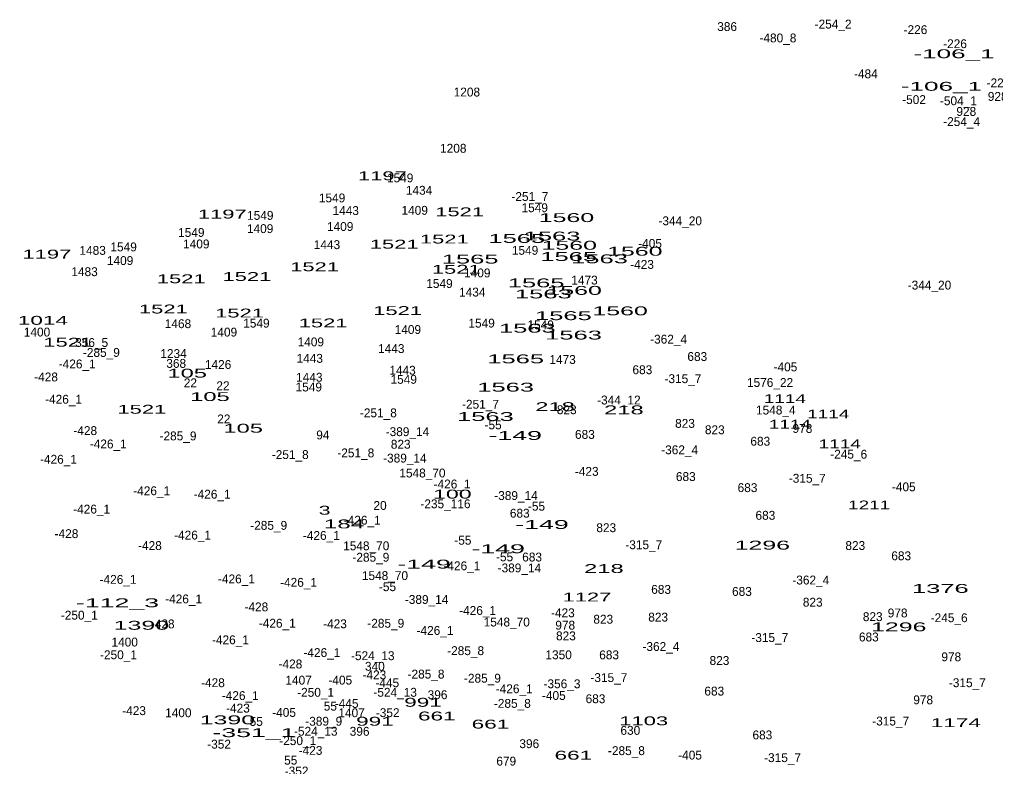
# Model space of a CAD drawing. Extents: x -660434 to -656144, y -997850 to -994016.
# Drawn here: x -659469.4 to -659029.2, y -995192.7 to -994855.8 of the extents above; entities that cross this region are included whole.
import ezdxf
from ezdxf.enums import TextEntityAlignment as Align

# ---------------------------------------------------------------- set-up
doc = ezdxf.new("R2010")
doc.units = 0
doc.header["$LTSCALE"] = 1.6
doc.layers.add('24', color=7, linetype='Continuous')

msp = doc.modelspace()

# ---------------------------------------------------------------- texts
at = {"layer": '24'}
for s, p in [('-254_2', (-659102.467, -994859.81)), ('386', (-659150.263, -994860.94)), ('-226', (-659065.33, -994862.33)), ('-480_8', (-659127.341, -994866.07)), ('-226', (-659047.47, -994868.67)), ('-484', (-659087.693, -994882.26)), ('-226', (-659027.89, -994886.34)), ('1208', (-659267.624, -994890.47)), ('-502', (-659065.959, -994893.88)), ('-504_1', (-659045.954, -994894.4)), ('928', (-659028.223, -994892.44)), ('928', (-659042.393, -994899.22)), ('-254_4', (-659044.491, -994903.8)), ('1208', (-659273.764, -994915.83)), ('1549', (-659297.71, -994929.2)), ('1434', (-659289.199, -994934.78)), ('1549', (-659328.43, -994938.23)), ('-251_7', (-659239.222, -994937.59)), ('1443', (-659322.269, -994943.94)), ('1409', (-659291.164, -994943.82)), ('1549', (-659237.03, -994942.65)), ('1549', (-659360.8, -994946.1)), ('1409', (-659360.864, -994952.08)), ('1409', (-659324.764, -994951.12)), ('-344_20', (-659171.414, -994948.55)), ('1549', (-659391.91, -994953.79)), ('1549', (-659422.44, -994960.32)), ('1409', (-659389.664, -994958.99)), ('1443', (-659330.719, -994959.31)), ('-405', (-659185.023, -994958.75)), ('1483', (-659436.404, -994961.89)), ('1549', (-659241.39, -994961.85)), ('1409', (-659424.034, -994966.48)), ('-423', (-659188.619, -994968.22)), ('1483', (-659440.054, -994971.5)), ('1409', (-659262.944, -994972.05)), ('1549', (-659279.99, -994976.84)), ('1473', (-659214.58, -994975.28)), ('-344_20', (-659058.994, -994977.55)), ('1434', (-659265.189, -994980.69)), ('1468', (-659397.93, -994994.95)), ('1549', (-659362.55, -994994.7)), ('1549', (-659260.98, -994994.7)), ('1549', (-659234.35, -994995.47)), ('1400', (-659461.502, -994998.73)), ('1409', (-659377.184, -994998.75)), ('1409', (-659294.244, -994997.6)), ('-356_5', (-659437.738, -995003.44)), ('1409', (-659338.014, -995003.17)), ('-362_4', (-659176.652, -995001.93)), ('-285_9', (-659432.468, -995007.92)), ('1234', (-659399.934, -995008.44)), ('1443', (-659301.729, -995006.18)), ('683', (-659163.713, -995009.76)), ('-426_1', (-659443.376, -995013.12)), ('368', (-659398.723, -995012.87)), ('1426', (-659379.83, -995013.38)), ('1443', (-659338.489, -995010.59)), ('1473', (-659224.47, -995011.1)), ('1443', (-659296.639, -995015.96)), ('683', (-659188.483, -995015.72)), ('-405', (-659123.963, -995014.45)), ('-428', (-659457.419, -995018.98)), ('22', (-659392.327, -995021.6)), ('22', (-659377.637, -995022.94)), ('1443', (-659338.689, -995019.13)), ('1549', (-659296.11, -995020.05)), ('-315_7', (-659170.182, -995019.75)), ('1576_22', (-659130.889, -995021.47)), ('1549', (-659338.93, -995023.51)), ('-426_1', (-659449.526, -995029.04)), ('-251_7', (-659261.492, -995031.3)), ('-344_12', (-659199.074, -995029.39)), ('-251_8', (-659307.546, -995035.17)), ('823', (-659222.577, -995033.77)), ('1548_4', (-659128.308, -995033.91)), ('22', (-659377.247, -995037.92)), ('-55', (-659255.805, -995040.59)), ('823', (-659169.257, -995039.92)), ('-428', (-659439.749, -995043.18)), ('94', (-659332.587, -995045.14)), ('-389_14', (-659294.435, -995043.66)), ('683', (-659214.403, -995044.9)), ('823', (-659155.817, -995042.8)), ('978', (-659116.288, -995042.22)), ('-426_1', (-659429.366, -995049.21)), ('-285_9', (-659397.908, -995045.57)), ('823', (-659297.467, -995049.33)), ('683', (-659135.303, -995047.98)), ('-251_8', (-659347.296, -995054)), ('-251_8', (-659317.726, -995053.23)), ('-362_4', (-659171.662, -995051.84)), ('-245_6', (-659095.432, -995053.83)), ('-426_1', (-659451.826, -995056.11)), ('-389_14', (-659295.595, -995055.57)), ('1548_70', (-659287.671, -995062.3)), ('-423', (-659213.579, -995061.57)), ('683', (-659168.903, -995063.91)), ('-315_7', (-659114.112, -995064.69)), ('-426_1', (-659409.776, -995070.32)), ('-426_1', (-659274.316, -995067.27)), ('683', (-659141.063, -995068.91)), ('-405', (-659070.583, -995068.54)), ('-426_1', (-659382.516, -995071.86)), ('-389_14', (-659245.475, -995072.47)), ('-426_1', (-659436.856, -995078.59)), ('20', (-659306.781, -995076.96)), ('-235_116', (-659277.295, -995076.19)), ('683', (-659243.783, -995080.43)), ('-55', (-659236.225, -995077.28)), ('-426_1', (-659314.826, -995083.59)), ('683', (-659132.993, -995081.39)), ('-285_9', (-659357.008, -995085.91)), ('823', (-659204.777, -995086.98)), ('-428', (-659448.199, -995089.66)), ('-426_1', (-659391.346, -995090.3)), ('-426_1', (-659333.266, -995090.47)), ('-55', (-659269.435, -995092.64)), ('-428', (-659410.569, -995095.04)), ('1548_70', (-659313.011, -995095.14)), ('-315_7', (-659187.842, -995094.66)), ('823', (-659092.457, -995095.02)), ('-285_9', (-659310.928, -995100.31)), ('-55', (-659250.625, -995100.13)), ('683', (-659238.213, -995100.21)), ('683', (-659071.743, -995099.65)), ('-426_1', (-659269.876, -995104.16)), ('-389_14', (-659243.945, -995105.12)), ('-426_1', (-659424.946, -995110.28)), ('-426_1', (-659371.566, -995110.08)), ('1548_70', (-659304.571, -995108.59)), ('-362_4', (-659112.522, -995110.58)), ('-426_1', (-659343.536, -995111.62)), ('-55', (-659303.425, -995113.58)), ('683', (-659180.033, -995114.81)), ('-426_1', (-659395.376, -995119.11)), ('-389_14', (-659285.795, -995119.34)), ('683', (-659143.573, -995115.72)), ('-428', (-659362.569, -995122.7)), ('-426_1', (-659262.796, -995124.31)), ('823', (-659111.657, -995120.57)), ('-250_1', (-659442.42, -995126.42)), ('-423', (-659224.329, -995125.34)), ('823', (-659206.127, -995128.26)), ('823', (-659181.357, -995127.3)), ('823', (-659084.587, -995127.1)), ('978', (-659073.358, -995125.43)), ('-245_6', (-659050.122, -995127.58)), ('-428', (-659404.809, -995130.38)), ('-426_1', (-659353.136, -995130.06)), ('-423', (-659327.109, -995130.31)), ('-285_9', (-659304.208, -995130.08)), ('1548_70', (-659249.651, -995129.52)), ('978', (-659223.288, -995130.95)), ('-426_1', (-659374.256, -995137.55)), ('-426_1', (-659281.996, -995133.31)), ('823', (-659222.967, -995135.76)), ('-315_7', (-659131.012, -995136.54)), ('683', (-659086.353, -995136.27)), ('1400', (-659421.952, -995138.56)), ('-362_4', (-659180.112, -995140.56)), ('-250_1', (-659424.75, -995144.28)), ('-426_1', (-659333.016, -995143.32)), ('-524_13', (-659310.059, -995144.71)), ('-285_8', (-659268.192, -995142.44)), ('1350', (-659226.244, -995144.29)), ('683', (-659203.483, -995144.34)), ('978', (-659049.168, -995145.22)), ('-428', (-659347.209, -995148.44)), ('340', (-659309.125, -995149.5)), ('823', (-659153.707, -995146.89)), ('-423', (-659309.339, -995153.36)), ('-285_8', (-659286.052, -995153.01)), ('-285_9', (-659260.618, -995154.86)), ('-315_7', (-659203.592, -995154.59)), ('-428', (-659382.149, -995156.89)), ('1407', (-659343.524, -995155.75)), ('-405', (-659324.723, -995155.71)), ('-445', (-659303.523, -995156.93)), ('-426_1', (-659246.286, -995159.62)), ('-356_3', (-659224.728, -995157.37)), ('-315_7', (-659041.922, -995156.89)), ('-426_1', (-659369.846, -995162.72)), ('-250_1', (-659335.85, -995161.23)), ('-524_13', (-659299.969, -995161.22)), ('396', (-659280.858, -995162.31)), ('-405', (-659228.413, -995162.65)), ('683', (-659156.053, -995160.67)), ('-423', (-659370.879, -995168.34)), ('55', (-659329.207, -995167.46)), ('-445', (-659321.853, -995166.24)), ('-285_8', (-659247.132, -995166.22)), ('683', (-659209.623, -995164.12)), ('978', (-659061.838, -995164.62)), ('-423', (-659417.729, -995169.5)), ('1400', (-659397.762, -995170.45)), ('-405', (-659350.073, -995170.31)), ('1407', (-659319.624, -995170.44)), ('-352', (-659303.345, -995170.41)), ('55', (-659362.617, -995174.37)), ('-389_9', (-659332.193, -995174.28)), ('-315_7', (-659076.482, -995174.18)), ('-524_13', (-659335.779, -995178.79)), ('396', (-659316.008, -995178.82)), ('630', (-659193.907, -995178.39)), ('683', (-659134.353, -995180.45)), ('-352', (-659379.385, -995184.62)), ('-250_1', (-659343.91, -995183.03)), ('396', (-659239.488, -995184.4)), ('-423', (-659338.139, -995187.42)), ('-285_8', (-659195.672, -995187.54)), ('-405', (-659166.973, -995189.54)), ('55', (-659347.067, -995191.85)), ('679', (-659249.873, -995192.26)), ('-315_7', (-659125.252, -995190.7)), ('-352', (-659344.435, -995196.73))]:
    msp.add_text(s, height=4, dxfattribs=at).set_placement(p, align=Align.CENTER)
for s, width, p in [('-106_1', 2.2, (-659047.929, -994873.19)), ('-106_1', 2.2, (-659053.589, -994887.88)), ('1197', 1.85, (-659305.743, -994928.23)), ('1197', 1.85, (-659377.943, -994945.51)), ('1521', 1.85, (-659270.894, -994944.49)), ('1560', 2.1, (-659222.709, -994947.11)), ('1521', 1.85, (-659277.804, -994956.78)), ('1565', 2.15, (-659245.123, -994956.5)), ('1563', 2.15, (-659229.213, -994955.42)), ('1521', 1.85, (-659300.404, -994959.09)), ('1560', 2.1, (-659221.459, -994959.59)), ('1197', 1.85, (-659457.043, -994963.57)), ('1565', 2.15, (-659266.153, -994965.82)), ('1565', 2.15, (-659221.703, -994964.66)), ('1563', 2.15, (-659207.803, -994965.69)), ('1560', 2.1, (-659191.889, -994962.28)), ('1521', 1.85, (-659336.304, -994969.27)), ('1521', 1.85, (-659272.424, -994970.42)), ('1521', 1.85, (-659396.454, -994974.69)), ('1521', 1.85, (-659366.834, -994973.68)), ('1565', 2.15, (-659236.383, -994976.56)), ('1563', 2.15, (-659233.153, -994981.54)), ('1560', 2.1, (-659219.249, -994979.93)), ('1521', 1.85, (-659404.514, -994988.33)), ('1521', 1.85, (-659370.144, -994990.15)), ('1521', 1.85, (-659298.864, -994989.05)), ('1565', 2.15, (-659224.103, -994991.33)), ('1560', 2.1, (-659198.509, -994989.17)), ('1014', 1.9, (-659458.856, -994993.44)), ('1521', 1.85, (-659332.464, -994994.62)), ('1563', 2.15, (-659240.353, -994997)), ('1563', 2.15, (-659219.523, -995000.08)), ('1521', 1.85, (-659447.624, -995003.31)), ('1565', 2.15, (-659245.603, -995010.82)), ('105', 2, (-659393.764, -995017.27)), ('1563', 2.15, (-659250.143, -995023.58)), ('105', 2, (-659383.494, -995027.84)), ('1114', 1.6, (-659124.226, -995028.78)), ('1521', 1.85, (-659414.214, -995033.56)), ('218', 2, (-659227.867, -995032.38)), ('218', 2, (-659196.817, -995033.82)), ('1114', 1.6, (-659104.646, -995035.69)), ('1563', 2.15, (-659259.263, -995036.83)), ('1114', 1.6, (-659121.926, -995040.3)), ('105', 2, (-659368.514, -995042.11)), ('-149', 2.25, (-659245.831, -995045.38)), ('1114', 1.6, (-659099.466, -995049.14)), ('100', 1.95, (-659274.18, -995071.81)), ('3', 1.8, (-659331.791, -995079.1)), ('1211', 1.6, (-659086.21, -995076.73)), ('184', 2.05, (-659323.023, -995085.27)), ('-149', 2.25, (-659233.741, -995085.53)), ('-149', 2.25, (-659253.511, -995096.47)), ('1296', 2.1, (-659134.387, -995094.83)), ('-149', 2.25, (-659286.921, -995103.39)), ('218', 2, (-659205.837, -995105.39)), ('1376', 2.15, (-659054.117, -995114.37)), ('1127', 1.85, (-659213.479, -995118.25)), ('-112_3', 2.25, (-659425.197, -995120.84)), ('1390', 2.1, (-659414.439, -995131)), ('1296', 2.1, (-659072.857, -995131.7)), ('991', 1.9, (-659287.417, -995165.74)), ('661', 1.9, (-659281.187, -995171.91)), ('1390', 2.1, (-659375.649, -995173.64)), ('991', 1.9, (-659309.107, -995174.28)), ('661', 1.9, (-659256.987, -995175.56)), ('1103', 1.85, (-659187.87, -995174.09)), ('1174', 1.9, (-659047.115, -995174.94)), ('-351_1', 2.25, (-659363.637, -995179.42)), ('661', 1.9, (-659219.607, -995189.59))]:
    msp.add_text(s, height=4, dxfattribs=dict(at, width=width)).set_placement(p, align=Align.CENTER)

doc.saveas('drawing.dxf')
